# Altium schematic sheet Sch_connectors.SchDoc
size A
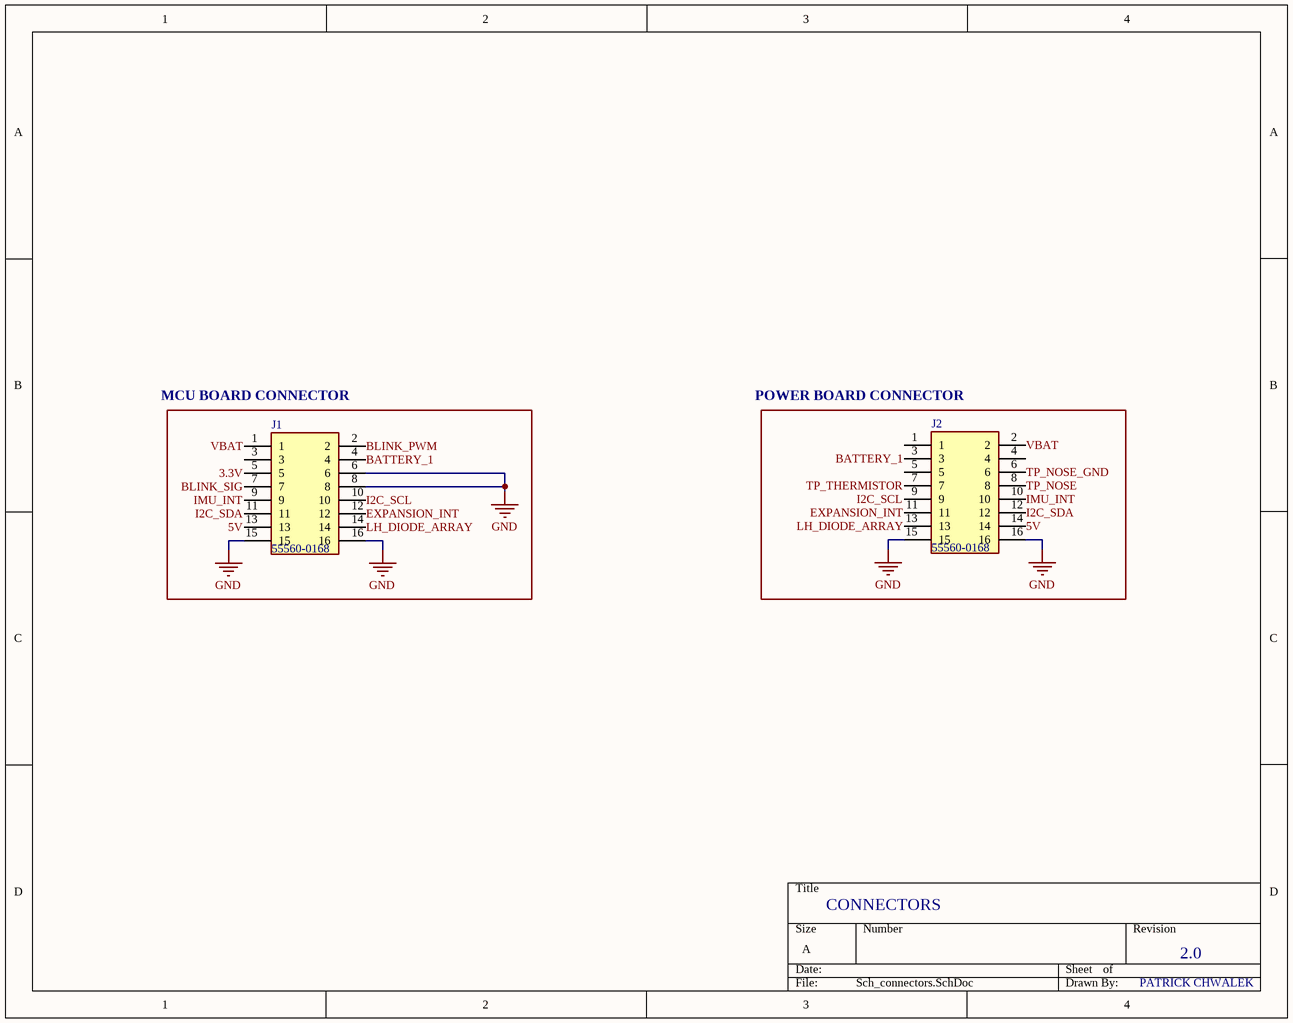
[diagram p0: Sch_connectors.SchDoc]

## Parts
J1  55560-0168  [555600168]
J2  55560-0168  [555600168]

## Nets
GND: J1.6 J1.8 J1.15 J1.16 J2.15 J2.16
3.3V: J1.5
5V: J1.13 J2.14
BATTERY_1: J1.4 J2.3
BLINK_PWM: J1.2
BLINK_SIG: J1.7
EXPANSION_INT: J1.12 J2.11
I2C_SCL: J1.10 J2.9
I2C_SDA: J1.11 J2.12
IMU_INT: J1.9 J2.10
LH_DIODE_ARRAY: J1.14 J2.13
TP_NOSE: J2.8
TP_NOSE_GND: J2.6
TP_THERMISTOR: J2.7
VBAT: J1.1 J2.2

Not connected (* = marked no-connect by the designer): J1 3; J2 1 4 5

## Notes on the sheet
- (near J1) MCU BOARD CONNECTOR
- (near J2) POWER BOARD CONNECTOR
- CONNECTORS
- 2.0
- PATRICK CHWALEK

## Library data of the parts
J1 J2 = 55560-0168: Connector; Manufacturer_Name: Molex; Allied_Number: 70374726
